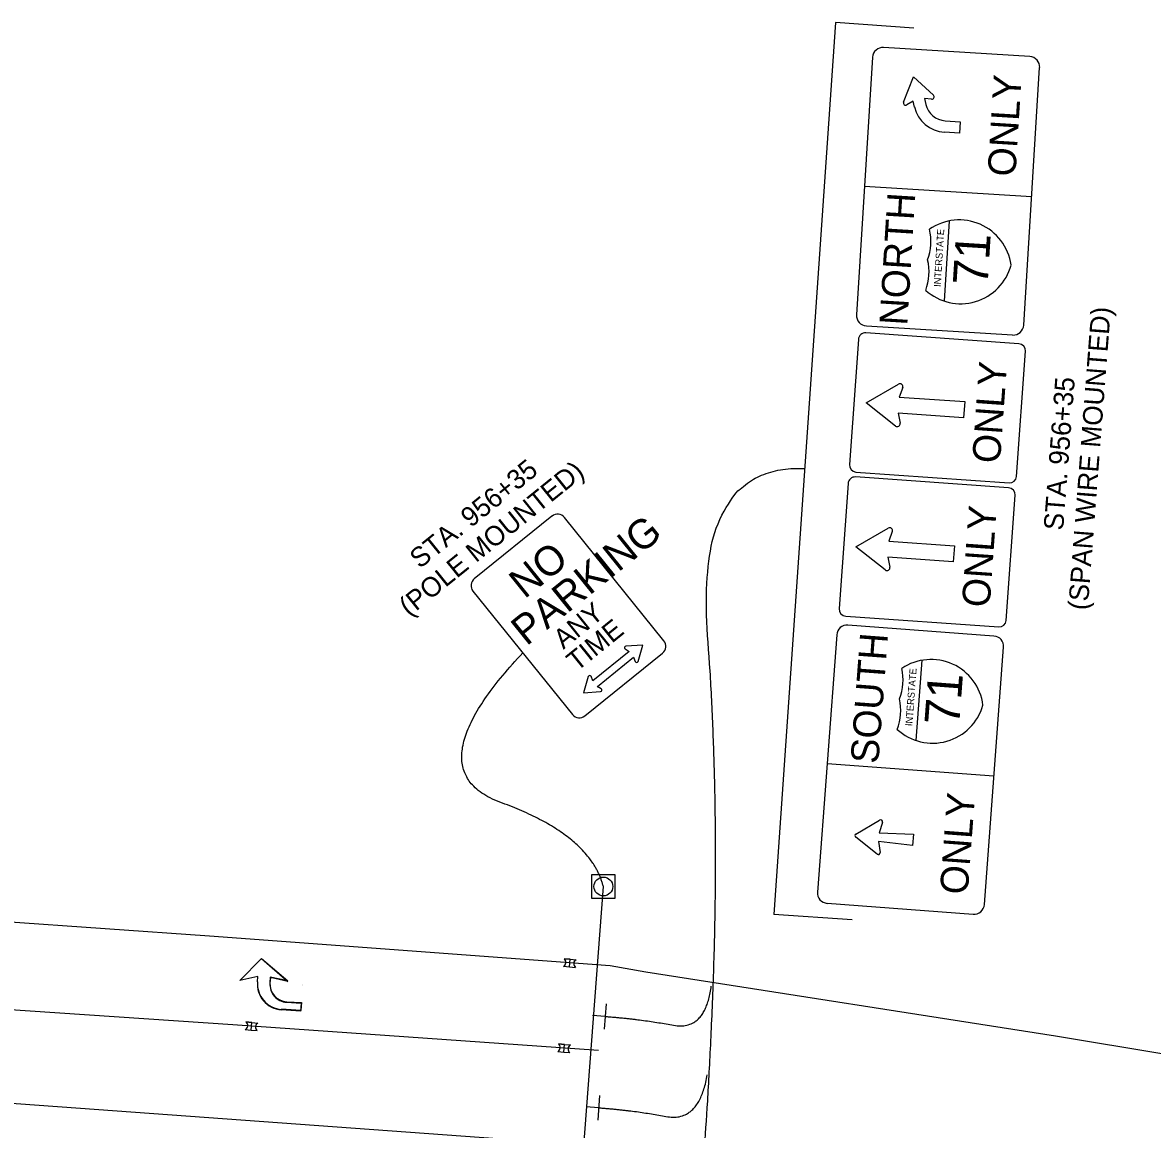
# Model space of a CAD drawing. Extents: x 1847379 to 1850904, y 217032 to 220169.
# Drawn here: x 1849700.4 to 1849844.7, y 218819 to 218960.4 of the extents above; entities that cross this region are included whole.
import ezdxf

# ---------------------------------------------------------------- set-up
doc = ezdxf.new("R2010")
doc.units = 0
for name, color, linetype in [('PM_P_Cells', 7, 'Continuous'), ('PM_P_Channelizing_Line', 7, 'Continuous'), ('PM_P_Edge_Line', 7, 'Continuous'), ('PM_P_Lane_Line', 7, 'Continuous'), ('PM_X_Cells', 7, 'Continuous'), ('SG_X_Poles', 7, 'Continuous'), ('SN_X_Public', 7, 'Continuous'), ('SN_X_Text', 7, 'Continuous')]:
    doc.layers.add(name, color=color, linetype=linetype)

msp = doc.modelspace()

# ---------------------------------------------------------------- linework, layer by layer
at = {"layer": 'PM_P_Cells'}
for p, q in [((1849728.2, 218838.02), (1849730.93, 218840.86)), ((1849730.93, 218840.86), (1849734.29, 218837.99)), ((1849769.5, 218839.85), (1849770.27, 218839.78)), ((1849769.5, 218839.85), (1849770.27, 218839.78)), ((1849770.36, 218840.75), (1849769.59, 218840.82)), ((1849769.59, 218840.82), (1849770.36, 218840.75)), ((1849770.27, 218839.78), (1849770.36, 218840.75)), ((1849770.36, 218840.75), (1849771.13, 218840.68)), ((1849730.47, 218838.55), (1849728.2, 218838.02)), ((1849730.43, 218837.88), (1849730.47, 218838.55)), ((1849732.07, 218838.45), (1849732.03, 218837.75)), ((1849734.29, 218837.99), (1849732.07, 218838.45)), ((1849770.27, 218839.78), (1849771.04, 218839.71)), ((1849728.2, 218838.02), (1849728.2, 218838.02)), ((1849736.18, 218837.54), (1849736.18, 218837.54)), ((1849735.98, 218834.21), (1849733.51, 218834.36)), ((1849734.18, 218835.32), (1849736.04, 218835.21)), ((1849736.04, 218835.21), (1849735.98, 218834.21)), ((1849729.73, 218832.68), (1849728.96, 218832.75)), ((1849728.96, 218832.75), (1849729.73, 218832.68)), ((1849729.64, 218831.71), (1849729.73, 218832.68)), ((1849729.73, 218832.68), (1849730.5, 218832.61)), ((1849728.88, 218831.78), (1849729.64, 218831.71)), ((1849728.88, 218831.78), (1849729.64, 218831.71)), ((1849729.64, 218831.71), (1849730.41, 218831.64)), ((1849769.63, 218829.88), (1849768.87, 218829.95)), ((1849768.87, 218829.95), (1849769.63, 218829.88)), ((1849769.55, 218828.9), (1849769.63, 218829.88)), ((1849769.63, 218829.88), (1849770.4, 218829.81)), ((1849768.78, 218828.97), (1849769.55, 218828.9)), ((1849768.78, 218828.97), (1849769.55, 218828.9)), ((1849769.55, 218828.9), (1849770.31, 218828.84))]:
    msp.add_line(p, q, dxfattribs=at)
for centre, radius, start, end in [((1849769.24, 218840.36), 0.576, 296.8063, 52.8586), ((1849769.24, 218840.36), 0.576, 296.8063, 52.8586), ((1849771.39, 218840.17), 0.576, 116.8063, 232.8586), ((1849733.71, 218837.63), 3.28, 175.6389, 266.5474), ((1849734.32, 218837.61), 2.3, 176.5474, 266.5474), ((1849728.62, 218832.29), 0.576, 296.8063, 52.8586), ((1849728.62, 218832.29), 0.576, 296.8063, 52.8586), ((1849730.76, 218832.1), 0.576, 116.8063, 232.8586), ((1849768.52, 218829.49), 0.576, 296.8063, 52.8586), ((1849768.52, 218829.49), 0.576, 296.8063, 52.8586), ((1849770.66, 218829.29), 0.576, 116.8063, 232.8586)]:
    msp.add_arc(centre, radius, start, end, dxfattribs=at)
at = {"layer": 'PM_P_Channelizing_Line'}
msp.add_lwpolyline([(1849773.98, 218829.08), (1849727.27, 218832.37), (1849675.5, 218835.87), (1849624.87, 218839.56), (1849609.96, 218840.55)], dxfattribs=at)
at = {"layer": 'PM_P_Edge_Line'}
msp.add_lwpolyline([(1849891.07, 218821.31), (1849889.22, 218821.46), (1849832.32, 218830.92), (1849780.01, 218839.12), (1849775.45, 218839.9), (1849724.32, 218843.71), (1849670.97, 218847.45), (1849610.73, 218851.87), (1849610.54, 218851.85)], dxfattribs=at)
at = {"layer": 'PM_P_Lane_Line'}
msp.add_lwpolyline([(1849608.99, 218828.81), (1849660.31, 218825.18), (1849710.18, 218821.58), (1849761.09, 218817.87), (1849808.06, 218814.41), (1849858.45, 218811.1), (1849907.69, 218807.67), (1849958.4, 218803.79), (1850015.55, 218799.15), (1850068.16, 218794.66), (1850119.07, 218790.16), (1850168.5, 218785.91), (1850217.76, 218781.65), (1850267.02, 218777.03), (1850317.3, 218772.15), (1850366.38, 218767.35), (1850416.59, 218762.59), (1850466.65, 218757.55), (1850517.86, 218752.55), (1850566.57, 218747.88), (1850616.29, 218742.91), (1850664.9, 218737.75)], dxfattribs=at)
at = {"layer": 'PM_X_Cells'}
for p, q in [((1849728.2, 218838.02), (1849730.96, 218840.83)), ((1849730.96, 218840.83), (1849734.29, 218837.93)), ((1849730.48, 218838.53), (1849728.2, 218838.02)), ((1849730.43, 218837.86), (1849730.48, 218838.53)), ((1849732.08, 218838.42), (1849732.03, 218837.71)), ((1849734.29, 218837.93), (1849732.08, 218838.42)), ((1849728.2, 218838.02), (1849728.2, 218838.02)), ((1849736.18, 218837.46), (1849736.18, 218837.46)), ((1849735.94, 218834.13), (1849733.47, 218834.31)), ((1849734.16, 218835.26), (1849736.01, 218835.13)), ((1849736.01, 218835.13), (1849735.94, 218834.13))]:
    msp.add_line(p, q, dxfattribs=at)
for centre, radius, start in [((1849733.7, 218837.58), 3.28, 175.0717), ((1849734.32, 218837.55), 2.3, 175.9802)]:
    msp.add_arc(centre, radius, start, 265.9802, dxfattribs=at)
at = {"layer": 'SG_X_Poles'}
msp.add_lwpolyline([(1849773.1, 218848.54), (1849776.1, 218848.54), (1849776.1, 218851.54), (1849773.1, 218851.54)], close=True, dxfattribs=at)
msp.add_circle((1849774.6, 218850.04), 1.2, dxfattribs=at)
at = {"layer": 'SN_X_Public'}
for p, q in [((1849812.94, 218950.23), (1849814.19, 218953.44)), ((1849814.19, 218953.44), (1849816.74, 218951.12)), ((1849814.16, 218950.33), (1849813.37, 218949.87)), ((1849814.33, 218949.6), (1849814.16, 218950.33)), ((1849816.52, 218950.61), (1849815.6, 218950.67)), ((1849815.6, 218950.67), (1849815.77, 218949.94)), ((1849816.19, 218947.92), (1849816.19, 218947.92)), ((1849816.19, 218947.92), (1849816.19, 218947.92)), ((1849818.24, 218947.85), (1849820.17, 218947.73)), ((1849820.17, 218947.73), (1849820.08, 218946.25)), ((1849820.08, 218946.25), (1849818.15, 218946.37)), ((1849807.96, 218939.51), (1849829.29, 218938.19)), ((1849818.18, 218924.8), (1849818.82, 218935.06)), ((1849821.34, 218929.76), (1849821.34, 218929.76)), ((1849808.15, 218911.81), (1849812.28, 218914.21)), ((1849812.82, 218913.76), (1849812.37, 218912.56)), ((1849812.37, 218912.56), (1849820.74, 218911.97)), ((1849820.74, 218911.97), (1849820.59, 218909.89)), ((1849811.9, 218908.86), (1849808.15, 218911.81)), ((1849820.59, 218909.89), (1849812.23, 218910.48)), ((1849812.23, 218910.48), (1849812.49, 218909.23)), ((1849806.84, 218893.42), (1849810.97, 218895.82)), ((1849811.5, 218895.37), (1849811.06, 218894.16)), ((1849810.59, 218890.47), (1849806.84, 218893.42)), ((1849811.06, 218894.16), (1849819.43, 218893.57)), ((1849819.43, 218893.57), (1849819.28, 218891.5)), ((1849819.28, 218891.5), (1849810.92, 218892.09)), ((1849810.92, 218892.09), (1849811.18, 218890.84)), ((1849777.38, 218880.39), (1849777.88, 218880.06)), ((1849779.63, 218880.87), (1849777.47, 218880.73)), ((1849779.03, 218878.79), (1849779.63, 218880.87)), ((1849773.84, 218875.6), (1849778.47, 218879.33)), ((1849778.47, 218879.33), (1849778.46, 218879.33)), ((1849778.47, 218879.33), (1849778.68, 218878.78)), ((1849814.53, 218868.69), (1849815.3, 218878.94)), ((1849775.75, 218877.59), (1849775.75, 218877.59)), ((1849772.68, 218876.87), (1849772.08, 218874.79)), ((1849773.24, 218876.33), (1849773.03, 218876.89)), ((1849772.08, 218874.79), (1849774.24, 218874.93)), ((1849774.33, 218875.27), (1849773.83, 218875.6)), ((1849773.83, 218875.6), (1849773.84, 218875.6)), ((1849817.75, 218873.6), (1849817.75, 218873.6)), ((1849803.17, 218865.76), (1849824.48, 218864.17)), ((1849806.85, 218856.75), (1849809.87, 218858.52)), ((1849810.23, 218858.24), (1849809.81, 218856.89)), ((1849809.55, 218854.17), (1849806.82, 218856.36)), ((1849814.08, 218855.28), (1849809.73, 218855.78)), ((1849809.73, 218855.78), (1849809.94, 218854.39)), ((1849809.81, 218856.89), (1849814.19, 218856.75)), ((1849810.17, 218856.31), (1849810.17, 218856.31)), ((1849814.19, 218856.75), (1849814.08, 218855.28)), ((1849766.69, 218744.22), (1849774.6, 218850.04)), ((1849774.94, 218835.04), (1849774.7, 218831.84)), ((1849774.82, 218833.44), (1849773.22, 218833.56)), ((1849774.12, 218823.37), (1849773.88, 218820.18)), ((1849774, 218821.78), (1849772.4, 218821.9))]:
    msp.add_line(p, q, dxfattribs=at)
for points in [[(1849829.06, 218956.05), (1849810.39, 218957.2)], [(1849808.98, 218955.95), (1849806.94, 218923.06)], [(1849828.28, 218921.74), (1849830.31, 218954.63)], [(1849827.66, 218919.36), (1849808.12, 218920.75)], [(1849808.19, 218921.65), (1849826.86, 218920.49)], [(1849807.16, 218919.92), (1849806.03, 218903.93)], [(1849827.35, 218902.42), (1849828.49, 218918.41)], [(1849826.35, 218900.97), (1849806.81, 218902.35)], [(1849806.86, 218902.98), (1849826.4, 218901.59)], [(1849805.85, 218901.53), (1849804.72, 218885.54)], [(1849826.04, 218884.03), (1849827.18, 218900.02)], [(1849768.04, 218897.36), (1849758.12, 218889.36)], [(1849782.33, 218881.42), (1849769.63, 218897.19)], [(1849757.95, 218887.78), (1849770.65, 218872.01)], [(1849805.55, 218884.58), (1849825.09, 218883.2)], [(1849824.48, 218882.03), (1849805.83, 218883.43)], [(1849804.4, 218882.19), (1849801.94, 218849.33)], [(1849823.25, 218847.74), (1849825.71, 218880.6)], [(1849772.24, 218871.84), (1849782.16, 218879.84)], [(1849777.88, 218880.06), (1849773.25, 218876.33)], [(1849803.17, 218847.9), (1849821.82, 218846.51)]]:
    msp.add_lwpolyline(points, dxfattribs=at)
for centre, radius, start, end in [((1849810.31, 218955.87), 1.34, 86.4583, 176.4583), ((1849828.98, 218954.71), 1.34, 356.4583, 86.4583), ((1849816.54, 218950.9), 0.297, 265.8232, 47.7013), ((1849813.22, 218950.12), 0.297, 158.6688, 300.5469), ((1849818.41, 218950.56), 4.19, 193.185, 266.4583), ((1849818.41, 218950.56), 2.71, 193.185, 266.4583), ((1849820.05, 218928.5), 6.68, 7.9952, 124.7893), ((1849809.75, 218932.43), 6.68, 339.4673, 13.4492), ((1849809.51, 218928.53), 6.68, 339.4673, 13.4492), ((1849820.22, 218931.16), 6.68, 228.1272, 344.9213), ((1849808.27, 218922.98), 1.34, 176.4583, 266.4583), ((1849808.05, 218919.86), 0.891, 85.9524, 175.9524), ((1849826.94, 218921.82), 1.34, 266.4583, 356.4583), ((1849827.6, 218918.47), 0.891, 355.9524, 85.9524), ((1849812.47, 218913.89), 0.371, 339.9081, 120.1434), ((1849812.13, 218909.15), 0.371, 231.7614, 11.9968), ((1849806.92, 218903.87), 0.891, 175.9524, 265.9524), ((1849806.74, 218901.46), 0.891, 85.9524, 175.9524), ((1849826.47, 218902.48), 0.891, 265.9524, 355.9524), ((1849826.29, 218900.08), 0.891, 355.9524, 85.9524), ((1849768.75, 218896.48), 1.12, 38.8676, 128.8676), ((1849811.16, 218895.5), 0.371, 339.9081, 120.1434), ((1849810.82, 218890.76), 0.371, 231.7614, 11.9968), ((1849758.82, 218888.48), 1.12, 128.8676, 218.8676), ((1849805.61, 218885.47), 0.891, 175.9524, 265.9524), ((1849805.73, 218882.09), 1.34, 85.7255, 175.7255), ((1849825.16, 218884.09), 0.891, 265.9524, 355.9524), ((1849824.38, 218880.7), 1.34, 355.7255, 85.7255), ((1849777.48, 218880.55), 0.182, 93.7884, 236.5054), ((1849781.46, 218880.72), 1.12, 308.8676, 38.8676), ((1849778.85, 218878.84), 0.182, 201.2298, 343.9469), ((1849816.45, 218872.36), 6.68, 7.2625, 124.0566), ((1849806.19, 218876.43), 6.68, 338.7346, 12.7165), ((1849772.86, 218876.82), 0.182, 21.2298, 163.9469), ((1849774.23, 218875.12), 0.182, 273.7884, 56.5054), ((1849805.9, 218872.53), 6.68, 338.7346, 12.7165), ((1849816.65, 218875.03), 6.68, 227.3945, 344.1886), ((1849771.53, 218872.71), 1.12, 218.8676, 308.8676), ((1849810, 218858.31), 0.24, 342.7493, 120.2226), ((1849806.97, 218856.55), 0.24, 121.6319, 229.8192), ((1849809.7, 218854.36), 0.24, 231.2284, 8.7017), ((1849803.27, 218849.23), 1.34, 175.7255, 265.7255), ((1849821.92, 218847.84), 1.34, 265.7255, 355.7255)]:
    msp.add_arc(centre, radius, start, end, dxfattribs=at)
at = {"layer": 'SN_X_Text'}
for p, q in [((1849804.26, 218960.38), (1849796.38, 218846.47)), ((1849814.23, 218959.69), (1849804.26, 218960.38)), ((1849806.36, 218845.78), (1849796.38, 218846.47))]:
    msp.add_line(p, q, dxfattribs=at)
for points in [[(1849772.39, 218798.65), (1849784.27, 218797.71), (1849787.59, 218811.21), (1849789.54, 218860.25), (1849786.3, 218904.05), (1849800.32, 218903.43)], [(1849774.6, 218850.04), (1849772.95, 218856.6), (1849750.24, 218864.87), (1849764.3, 218879.89)], [(1849774.82, 218833.44), (1849779.29, 218833.13), (1849787.63, 218831.54), (1849788.38, 218837.32)], [(1849774, 218821.78), (1849778.47, 218821.46), (1849786.82, 218819.88), (1849787.87, 218825.98)]]:
    msp.add_open_spline(points, degree=2, dxfattribs=at)

# ---------------------------------------------------------------- texts
at = {"layer": 'SN_X_Public'}
for s, height, rotation, p in [('ONLY', 3.562, 86.4583, (1849827.21, 218940.65)), ('NORTH', 3.562, 86.4583, (1849813.4, 218921.64)), ('INTERSTATE', 0.891, 86.4583, (1849817.68, 218926.6)), ('71', 4.453, 86.4583, (1849823.66, 218926.72)), ('ONLY', 3.562, 85.9524, (1849825.24, 218904.02)), ('ONLY', 3.562, 85.9524, (1849823.92, 218885.62)), ('PARKING', 3.75, 38.8676, (1849764.78, 218880.68)), ('NO', 3.75, 38.8676, (1849764.53, 218886.7)), ('ANY', 2.5, 38.8676, (1849769.5, 218880.27)), ('TIME', 2.5, 38.8676, (1849771.2, 218877.43)), ('SOUTH', 3.562, 85.7255, (1849809.71, 218865.66)), ('INTERSTATE', 0.891, 85.7255, (1849814.05, 218870.5)), ('71', 4.453, 85.7255, (1849820.03, 218870.54)), ('ONLY', 3.562, 85.7255, (1849821.11, 218848.94))]:
    msp.add_text(s, height=height, rotation=rotation, dxfattribs=at).set_placement(p)
at = {"layer": 'SN_X_Text'}
for s, rotation, p in [('(SPAN WIRE MOUNTED)', 85.5938, (1849836.44, 218885.29)), ('STA. 956+35', 85.5938, (1849833.31, 218895.47)), ('(POLE MOUNTED)', 38.8676, (1849749.8, 218884.45)), ('STA. 956+35', 38.8676, (1849751.16, 218890.56))]:
    msp.add_text(s, height=2.5, rotation=rotation, dxfattribs=at).set_placement(p)

doc.saveas('drawing.dxf')
